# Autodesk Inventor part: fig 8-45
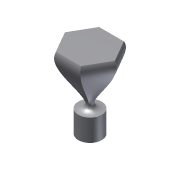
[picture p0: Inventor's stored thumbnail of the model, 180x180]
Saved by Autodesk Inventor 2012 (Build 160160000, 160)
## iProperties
Created: 2004-05
Part Number: fig 8-45
Document SubType Name: Modeling
Designer: CADCIM Technologies
Manufacturer: Standard
Standards Organization: Custom
Density: 1 g/cm^3
Material: Default
Author: CADCIM Technologies
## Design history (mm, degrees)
sketch "Sketch1"
  geometry: C1 r 16.344 at (0, 0)
  constraints: 1 centre point
extrude "Extrusion1" new body sketch "Sketch1" distance "d0" = 30.75; taper "d1" = 0 deg
workplane "Work Plane1"
sketch "Sketch2"
  geometry: L1 (34.788, 0)-(17.394, -30.128); L2 (17.394, -30.128)-(-17.394, -30.128); L3 (-17.394, -30.128)-(-34.788, 0); L4 (-34.788, 0)-(-17.394, 30.128); L5 (-17.394, 30.128)-(17.394, 30.128); L6 (17.394, 30.128)-(34.788, 0); 2 further points
  constraints: 12 end point, 1 coincident, 12 other
loft "Loft2" sketch "Sketch2" dims "d9" = 15, "d10" = 90 deg, "d11" = 80, "d12" = 120 deg
  node "Edges2"
body "Solid1"
other parameters: "d2" = 75
